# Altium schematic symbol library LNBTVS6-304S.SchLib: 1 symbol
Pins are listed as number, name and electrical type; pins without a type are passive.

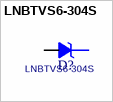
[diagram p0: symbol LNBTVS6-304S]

## LNBTVS6-304S
designator D?
footprint ST_SMC
pins: 1 K, 2 A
